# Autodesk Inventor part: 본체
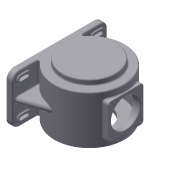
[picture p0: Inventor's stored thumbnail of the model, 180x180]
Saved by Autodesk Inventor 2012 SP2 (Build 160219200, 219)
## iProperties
Created: 2015-06
Part Number: 본체
Material: 알루미늄-6061
Document SubType Name: Modeling
Designer: Administrator
Density: 2.71 g/cm^3
Mass: 3288.7 g
Surface Area: 2309.35 cm^2
Volume: 1213.54 cm^3
Author: Administrator
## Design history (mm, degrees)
sketch "스케치1"
  geometry: L1 (-115, -99)-(115, -99); L2 (115, -99)-(115, -85); L3 (115, -85)-(-115, -85); L4 (-115, -85)-(-115, -99); L5 (-115, -99)-(115, -85); L6 (0, 0)-(0, -92); C1 r 85 at (0, 0); 1 further point
  constraints: 12 end point, 3 parallel, 1 centre point, 1 coincident, 1 horizontal, 1 midpoint, 1 perpendicular
  dimensions: "d0" = 170 diameter of C1; "d57" = 230 distance of L3.end L2.end; "d58" = 14 distance of L2.end L1.end; "d59" = 92 distance of L6.start L6.end
extrude "돌출1" new body sketch "스케치1" stored distance "d1" = 118; taper "d2" = 0 deg
sketch "스케치2"
  geometry: C1 r 85 at (0, 0) reference; C2 r 65 at (0, 0)
  constraints: 1 centre point, 1 coincident
  dimensions: "d3" = 130 diameter of C2
extrude "돌출2" join sketch "스케치2" distance "d4" = 13; taper "d5" = 0 deg
sketch "스케치3"
  geometry: C1 r 85 at (0, 0) reference; C2 r 65 at (0, 0)
  constraints: 1 centre point, 1 coincident
  dimensions: "d6" = 130 diameter of C2
extrude "돌출3" join sketch "스케치3" distance "d7" = 3; taper "d8" = 0 deg
node "작업 평면1"
sketch "스케치4"
  geometry: L1 (-42.5, 42.5)-(42.5, 42.5); L2 (42.5, 42.5)-(42.5, -42.5); L3 (42.5, -42.5)-(-42.5, -42.5); L4 (-42.5, -42.5)-(-42.5, 42.5); L5 (-42.5, -42.5)-(42.5, 42.5); 2 further points
  constraints: 10 end point, 2 parallel, 1 coincident, 1 horizontal, 1 midpoint, 1 perpendicular
  dimensions: "d10" = 85 distance of L2.end L3.end; "d11" = 85 distance of L1.end L2.end
extrude "돌출4" join sketch "스케치4" stored distance "d12" = 3; taper "d13" = 0 deg
extrude "돌출5" join sketch "스케치4" distance "d14" = 3; taper "d15" = 0 deg
sketch "스케치6"
  geometry: C1 r 65 at (0, 0) reference; 1 further point
  constraints: 1 coincident
hole "구멍1" sketch "스케치6" at (0, 0) diameter "d19" = 95; stored, may be unused: countersink angle "d23" = 90 deg, drill point angle "d25" = 0 deg; dims "d20" = 6, "d21" = 4, "d22" = 2, "d24" = 11
chamfer "모따기1" distance "d26" = 1; stored, may be unused: second distance "d27" = 2, angle "d28" = 45 deg
sketch "스케치9"
  geometry: 2 further points
  constraints: 1 coincident
hole "구멍4" sketch "스케치9" at (0, 0) diameter "d47" = 70; stored, may be unused: countersink angle "d51" = 90 deg, drill point angle "d53" = 0 deg; dims "d48" = 6, "d49" = 4, "d50" = 2, "d52" = 50
chamfer "모따기3" distance "d54" = 1; stored, may be unused: second distance "d55" = 2, angle "d56" = 45 deg
node "작업 평면2"
sketch "스케치10"
  geometry: L1 (-115, 59)-(115, 59); L2 (115, 59)-(115, -59); L3 (115, -59)-(-115, -59); L4 (-115, -59)-(-115, 59); L5 (-115, -59)-(115, 59); 2 further points
  constraints: 10 end point, 2 parallel, 1 coincident, 1 horizontal, 1 midpoint, 1 perpendicular
  dimensions: "d61" = 230 distance of L2.end L3.end; "d62" = 118 distance of L1.end L2.end
extrude "돌출7" join sketch "스케치10" distance "d63" = 14; taper "d64" = 0 deg
sketch "스케치11"
  geometry: C1 r 77 at (0, 0); 1 further point
  constraints: 1 centre point, 1 coincident
  dimensions: "d65" = 154 diameter of C1
extrude "돌출8" cut sketch "스케치11" stored distance "d66" = 102; taper "d67" = 0 deg
sketch "스케치12"
  geometry: C1 r 77 at (0, 0) reference; C2 r 31 at (0, 0)
  constraints: 1 centre point, 1 coincident
  dimensions: "d68" = 62 diameter of C2
extrude "돌출9" join sketch "스케치12" distance "d69" = 3.5; taper "d70" = 0 deg
feature "면 기울기1" dims angle "d71" = 25 deg
sketch "스케치13"
  geometry: C1 r 31 at (0, 0) reference; 1 further point
  constraints: 1 coincident
hole "구멍5" sketch "스케치13" at (0, 0) diameter "d72" = 47; stored, may be unused: countersink angle "d76" = 90 deg, drill point angle "d78" = 0 deg; dims "d73" = 6, "d74" = 4, "d75" = 2, "d77" = 14
chamfer "모따기4" distance "d79" = 1; stored, may be unused: second distance "d80" = 2, angle "d81" = 45 deg
fillet "모깎기2" dims "d82" = 0.3
sketch "스케치14"
  geometry: C1 r 23.2 at (0, 0) reference; 1 further point
  constraints: 1 coincident
hole "구멍6" sketch "스케치14" at (0, 0) diameter "d83" = 30; stored, may be unused: countersink angle "d87" = 90 deg, drill point angle "d89" = 0 deg; dims "d84" = 6, "d85" = 4, "d86" = 2, "d88" = 3
fillet "모깎기3" dims "d90" = 3
sketch "스케치15"
  geometry: L1 (-71, 46.733)-(-71, 115) reference; L2 (-71, 115)-(-71, 109); L3 (-71, 109)-(-4.703, 84.87); L4 (-71, 46.733)-(-71, 109); A1 r 85 centre (0, 0) between (-71, -46.733) and (-71, 46.733) reference; A2 r 85 centre (0, 0) between (-4.703, 84.87) and (-71, 46.733); 1 further point
  constraints: 7 end point, 3 point on circle, 1 centre point, 1 coincident, 1 collinear, 1 point on line
  dimensions: "d91" = 6 distance of L1.end L2.end; "d92" = 110 deg angle of L3 L1
extrude "돌출10" join sketch "스케치15" stored distance "d93" = 15; taper "d94" = 0 deg
fillet "모깎기4"
fillet "모깎기5"
sketch "스케치16"
  geometry: L1 (-59, 115)-(59, 115) reference; L2 (-7.5, 46.733)-(-59, 46.733) reference; L3 (0, 115)-(0, -115); L4 (-59, -115)-(59, -115) reference; L5 (41, 115)-(41, -115); L6 (-41, 115)-(-41, -115); L7 (59, 0)-(-59, 0); L8 (50, 97)-(50, 81); L9 (32, 81)-(32, 97); L10 (50, -81)-(50, -97); L11 (32, -97)-(32, -81); L12 (-32, 81)-(-32, 97); L13 (-50, 97)-(-50, 81); L14 (-50, -81)-(-50, -97); L15 (-32, -97)-(-32, -81); A1 r 9 centre (41, 97) between (50, 97) and (32, 97); A2 r 9 centre (41, -97) between (32, -97) and (50, -97); A3 r 9 centre (41, 81) between (32, 81) and (50, 81); A4 r 9 centre (41, -81) between (50, -81) and (32, -81); A5 r 9 centre (-41, 81) between (-50, 81) and (-32, 81); A6 r 9 centre (-41, 97) between (-32, 97) and (-50, 97); A7 r 9 centre (-41, -81) between (-32, -81) and (-50, -81); A8 r 9 centre (-41, -97) between (-50, -97) and (-32, -97); 2 further points
  constraints: 24 end point, 16 point on circle, 13 symmetric about line, 8 centre point, 5 tangent, 4 parallel, 3 midpoint, 3 point on line, 2 perpendicular, 1 horizontal alignment, 4 other
  dimensions: "d95" = 41 distance between parallel lines of L5 L3; "d96" = 41 distance between parallel lines of L6 L3; "d97" = 18 diameter of A2; "d98" = 18 diameter of A1; "d99" = 194 distance of A2.centre A1.centre; "d100" = 18 diameter of A3; "d102" = 16 distance of A3.centre A1.centre; "d103" = 16 distance of A2.centre A4.centre; "d104" = 16 distance of L8.start L8.end; "d105" = 9 radius of A4
extrude "돌출11" join sketch "스케치16" distance "d106" = 3; taper "d107" = 0 deg
fillet "모깎기6" dims "d108" = 3
sketch "스케치17"
  geometry: L1 (32, 81)-(32, 97) reference; L2 (45, 97)-(45, 81); L3 (37, 97)-(37, 81); L4 (-79.894, 0)-(117.106, 0); L5 (0, 142.737)-(0, -166.263); L6 (-45, 97)-(-45, 81); L7 (-37, 97)-(-37, 81); L8 (-37, -97)-(-37, -81); L9 (-45, -97)-(-45, -81); L10 (37, -97)-(37, -81); L11 (45, -97)-(45, -81); A1 r 9 centre (41, 97) between (50, 97) and (32, 97) reference; A2 r 9 centre (41, 81) between (32, 81) and (50, 81) reference; A3 r 4 centre (41, 97) between (45, 97) and (37, 97); A4 r 4 centre (41, 81) between (37, 81) and (45, 81); A5 r 4 centre (-41, 97) between (-37, 97) and (-45, 97); A6 r 4 centre (-41, 81) between (-45, 81) and (-37, 81); A7 r 4 centre (-41, -97) between (-45, -97) and (-37, -97); A8 r 4 centre (-41, -81) between (-37, -81) and (-45, -81); A9 r 4 centre (41, -81) between (45, -81) and (37, -81); A10 r 4 centre (41, -97) between (37, -97) and (45, -97); 7 further points
  constraints: 24 symmetric about line, 20 end point, 16 point on circle, 8 centre point, 8 coincident, 2 perpendicular, 2 point on line, 2 tangent, 1 parallel, 6 other
  dimensions: "d109" = 8 diameter of A3; "d110" = 8 diameter of A4; "d111" = 16 distance of L3.start L3.end
extrude "돌출12" cut sketch "스케치17" distance "d112" = 17; taper "d113" = 0 deg
sketch "스케치18"
  geometry: L1 (35.5, 35.5)-(-35.5, 35.5); L2 (-35.5, 35.5)-(-35.5, -35.5); L3 (-35.5, -35.5)-(35.5, -35.5); L4 (35.5, -35.5)-(35.5, 35.5); L5 (-35.5, -35.5)-(35.5, 35.5); C1 r 36 at (0, 0) reference; 5 further points
  constraints: 10 end point, 5 coincident, 2 parallel, 1 horizontal, 1 midpoint, 1 perpendicular
  dimensions: "d114" = 71 distance of L3.end L2.end; "d115" = 71 distance of L2.end L1.end
hole "구멍7" sketch "스케치18" at (-35.5, 35.5), (35.5, 35.5), (35.5, -35.5), (-35.5, -35.5) diameter "d116" = 3.242; stored, may be unused: countersink angle "d120" = 90 deg, drill point angle "d122" = 118 deg; dims "d117" = 10, "d118" = 4, "d119" = 2, "d121" = 13
sketch "스케치19"
  geometry: L1 (0, 115.025)-(0, -137.975); L2 (-129.487, 0)-(134.513, 0); C1 r 65 at (0, 0) reference; C2 r 48.5 at (0, 0) reference; A1 r 55 centre (0, 0) between (0, 55) and (55, 0); 2 further points
  constraints: 6 point on line, 4 end point, 4 point on circle, 1 centre point, 1 coincident, 1 perpendicular, 1 vertical
  dimensions: "d123" = 110 diameter of A1
hole "구멍8" sketch "스케치19" at (0, 55), (55, 0), (0, -55), (-55, 0) diameter "d124" = 3.242; stored, may be unused: countersink angle "d128" = 90 deg, drill point angle "d130" = 118 deg; dims "d125" = 30, "d126" = 4, "d127" = 2, "d129" = 20
node "작업축1"
fillet "모깎기7" dims "d135" = 3
fillet "모깎기8" dims "d136" = 3
fillet "모깎기9" dims "d137" = 3
fillet "모깎기10" dims "d138" = 7
fillet "모깎기11" dims "d139" = 3
fillet "모깎기12" dims "d140" = 3
fillet "모깎기13" dims "d141" = 3
fillet "모깎기14" dims "d142" = 3
fillet "모깎기15" dims "d143" = 3
fillet "모깎기16" dims "d144" = 3
node "작업 평면6"
  node "작업 평면5"
sketch "스케치21"
  geometry: L1 (-6.549, -40.533)-(-6.549, 40.533); L2 (-6.549, 40.533)-(6.549, 40.533); L3 (6.549, 40.533)-(6.549, -40.533); L4 (6.549, -40.533)-(-6.549, -40.533); L5 (0, -40.533)-(0, 40.533); L6 (-6.549, 0)-(6.549, 0); 2 further points
  constraints: 5 midpoint, 4 end point, 1 coincident, 2 other
feature "엠보싱2" sketch "스케치21" dims "d147" = 0.5, "d148" = 0
fillet "모깎기17" dims "d149" = 18
sketch "스케치22"
  geometry: L1 (-42.5, 0)-(-42.5, 35.5) reference; L2 (-42.5, -35.5)-(-42.5, 0) reference; L3 (35.5, -42.5)-(-35.5, -42.5) reference; L4 (42.5, 0)-(42.5, -35.5) reference; L5 (42.5, 35.5)-(42.5, 0) reference; L6 (-35.5, 42.5)-(35.5, 42.5) reference; C1 r 1.621 at (-35.5, -35.5) reference; C2 r 1.621 at (35.5, -35.5) reference; C3 r 1.621 at (35.5, 35.5) reference; C4 r 1.621 at (-35.5, 35.5) reference; C5 r 36 at (0, 0) reference; A1 r 7 centre (-35.5, 35.5) between (-35.5, 42.5) and (-42.5, 35.5) reference; A2 r 7 centre (-35.5, -35.5) between (-42.5, -35.5) and (-35.5, -42.5) reference; A3 r 7 centre (35.5, -35.5) between (35.5, -42.5) and (42.5, -35.5) reference; A4 r 7 centre (35.5, 35.5) between (42.5, 35.5) and (35.5, 42.5) reference; 1 further point
  constraints: 1 coincident
node "솔리드1"
mirror "대칭1"
other parameters: "d9" = 85, "d60" = -85, "d101" = 18, "d145" = -115 deg, "d146" = -85
